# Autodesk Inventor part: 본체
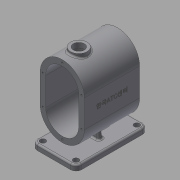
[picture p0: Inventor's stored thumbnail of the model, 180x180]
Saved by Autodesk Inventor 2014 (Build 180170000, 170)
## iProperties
Created: 2016-12
Part Number: 본체
Material: Aluminum 6061
Document SubType Name: Modeling
Designer: mduedu
Density: 1 g/cm^3
Appearance: Default
Author: mduedu
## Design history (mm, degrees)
sketch "스케치1"
  geometry: L1 (40, -25)-(40, 25); L2 (-40, 25)-(-40, -25); L3 (-40, -25)-(40, 25); L4 (40, -25)-(-40, 25); L5 (0, 25)-(0, -25); A1 r 40 centre (0, 25) between (40, 25) and (-40, 25); A2 r 40 centre (0, -25) between (-40, -25) and (40, -25); 1 further point
  constraints: 10 end point, 4 point on circle, 3 tangent, 2 centre point, 2 midpoint, 2 parallel, 1 vertical
  dimensions: "d0" = 130 dimension on A2 A1; "d2" = 80 distance between parallel lines of L1 L2
extrude "돌출1" new body sketch "스케치1" stored distance "d3" = 100; taper "d4" = 0 deg
feature "쉘1" dims "d5" = 10
sketch "스케치2"
  geometry: L1 (-75, 65)-(-85, 65); L2 (-85, 65)-(-85, -65); L3 (-85, -65)-(-75, -65); L4 (-75, -65)-(-75, 65); 2 further points
  constraints: 8 end point, 2 parallel, 1 horizontal, 1 horizontal alignment, 1 midpoint, 1 perpendicular
  dimensions: "d6" = 85 distance from line of L2 point (0, 0); "d7" = 130 distance of L1.end L2.end; "d8" = 10 distance of L2.end L3.end
extrude "돌출2" join sketch "스케치2" stored distance "d9" = 80; taper "d10" = 0 deg
fillet "모깎기1" dims "d11" = 10
sketch "스케치3"
  geometry: L1 (-10, 10)-(-10, 120) reference; L2 (60, 0)-(0, 0) reference; L3 (70, 120)-(70, 10) reference; L4 (0, 130)-(60, 130) reference; A1 r 10 centre (0, 120) between (0, 130) and (-10, 120) reference; A2 r 10 centre (0, 10) between (-10, 10) and (0, 0) reference; A3 r 10 centre (60, 10) between (60, 0) and (70, 10) reference; A4 r 10 centre (60, 120) between (70, 120) and (60, 130) reference; 5 further points
  constraints: 4 coincident
hole "구멍1" sketch "스케치3" at (60, 120), (60, 10), (0, 10), (0, 120) diameter "d12" = 10; stored, may be unused: countersink angle "d16" = 90 deg, drill point angle "d18" = 118 deg; dims "d13" = 6, "d14" = 4, "d15" = 2, "d17" = 8
sketch "스케치5"
  geometry: L1 (34, 35)-(26, 35); L2 (26, 35)-(26, 95); L3 (26, 95)-(34, 95); L4 (34, 95)-(34, 35); L5 (34, 35)-(26, 95); L6 (26, 35)-(34, 95); 1 further point
  constraints: 12 end point, 2 midpoint, 2 parallel, 1 horizontal, 1 perpendicular
  dimensions: "d22" = 8 distance of L2.end L3.end; "d24" = 60 distance of L1.end L2.end
extrude "돌출3" join sketch "스케치5" stored distance "d25" = 80; taper "d26" = 0 deg
feature "면 기울기1" dims angle "d27" = 5 deg
sketch "스케치6"
  geometry: L1 (-30, -75)-(30, -75) reference; L2 (-17.524, -60.957)-(-20, -75); A1 r 40 centre (0, -25) between (-40, -25) and (40, -25) reference; 1 further point
  constraints: 2 end point, 1 point on circle, 1 point on line
  dimensions: "d28" = 20 horizontal distance of A1.centre L2.end; "d29" = 80 deg angle of L2 L1
feature "리브1" sketch "스케치6" dims "d30" = 1, "d31" = 8, "d32" = 0, "d33" = 0, "d34" = 1, "d35" = 1
fillet "모깎기2" dims "d36" = 3
fillet "모깎기3" dims "d37" = 3, "d38" = 3
node "작업 평면1"
sketch "스케치9"
  geometry: 1 further point
sketch "스케치7"
  geometry: L1 (40, 50)-(-40, 50) reference; C1 r 15 at (0, 20); 1 further point
  constraints: 1 centre point, 1 vertical alignment
  dimensions: "d40" = 30 diameter of C1; "d41" = 30 distance from line of C1.centre L1
extrude "돌출4" join sketch "스케치7" stored distance "d42" = 80; taper "d43" = 0 deg
hole "구멍2" diameter "d46" = 20; stored, may be unused: countersink angle "d50" = 90 deg, drill point angle "d52" = 118 deg; dims "d44" = 10, "d45" = 10, "d47" = 6, "d48" = 4, "d49" = 2, "d51" = 8
fillet "모깎기4" dims "d53" = 3
node "작업 평면2"
sketch "스케치8"
  geometry: C1 r 15 at (0, 0) reference; C2 r 15 at (0, 0); 1 further point
  constraints: 1 centre point, 1 coincident
  dimensions: "d55" = 30 diameter of C2
extrude "돌출5" cut sketch "스케치8" stored distance "d56" = 80; taper "d57" = 0 deg
chamfer "모따기1" distance "d58" = 1; stored, may be unused: second distance "d59" = 2, angle "d60" = 45 deg
sketch "스케치10"
  geometry: 2 further points
  constraints: 1 coincident, 1 other
feature "엠보싱1" sketch "스케치10" dims "d0" = 130, "d2" = 80, "d61" = 0.5, "d62" = 0
sketch "스케치11"
  geometry: 1 further point
hole "구멍3" sketch "스케치11" at (0, 60) diameter "d63" = 3.242; stored, may be unused: countersink angle "d67" = 90 deg, drill point angle "d69" = 120 deg; dims "d64" = 8.6, "d65" = 4, "d66" = 2, "d68" = 10.6
sketch "스케치12"
  geometry: 1 further point
hole "구멍5" sketch "스케치12" at (0, 60) diameter "d70" = 3.242; stored, may be unused: countersink angle "d74" = 90 deg, drill point angle "d76" = 120 deg; dims "d71" = 8.6, "d72" = 4, "d73" = 2, "d75" = 10.6
node "솔리드1"
mirror "대칭1"
pattern_linear "직사각형 패턴1"
pattern_linear "직사각형 패턴2"
node "투영된 루프1"
sketch "스케치13"
  geometry: L1 (-40, 25)-(-40, -25) reference; L2 (40, -25)-(40, 25) reference; L3 (35, 25)-(35, -25); L4 (-35, -25)-(-35, 25); A1 r 40 centre (0, 25) between (40, 25) and (-40, 25) reference; A2 r 40 centre (0, -25) between (-40, -25) and (40, -25) reference; A3 r 35 centre (0, 25) between (35, 25) and (-35, 25); A4 r 35 centre (0, -25) between (-35, -25) and (35, -25); 2 further points
  constraints: 5 point on circle, 4 end point, 2 centre point, 3 other
  dimensions: "d77" = 5 distance between parallel lines of L3 L2
sketch "스케치14"
  geometry: L1 (-40, 25)-(-40, -25) reference; L2 (40, -25)-(40, 25) reference; L3 (35, 25)-(35, -25); L4 (-35, -25)-(-35, 25); A1 r 40 centre (0, 25) between (40, 25) and (-40, 25) reference; A2 r 40 centre (0, -25) between (-40, -25) and (40, -25) reference; A3 r 35 centre (0, 25) between (35, 25) and (-35, 25); A4 r 35 centre (0, -25) between (-35, -25) and (35, -25); 2 further points
  constraints: 5 point on circle, 4 end point, 2 centre point, 3 other
  dimensions: "d80" = 5 distance between parallel lines of L2 L3
